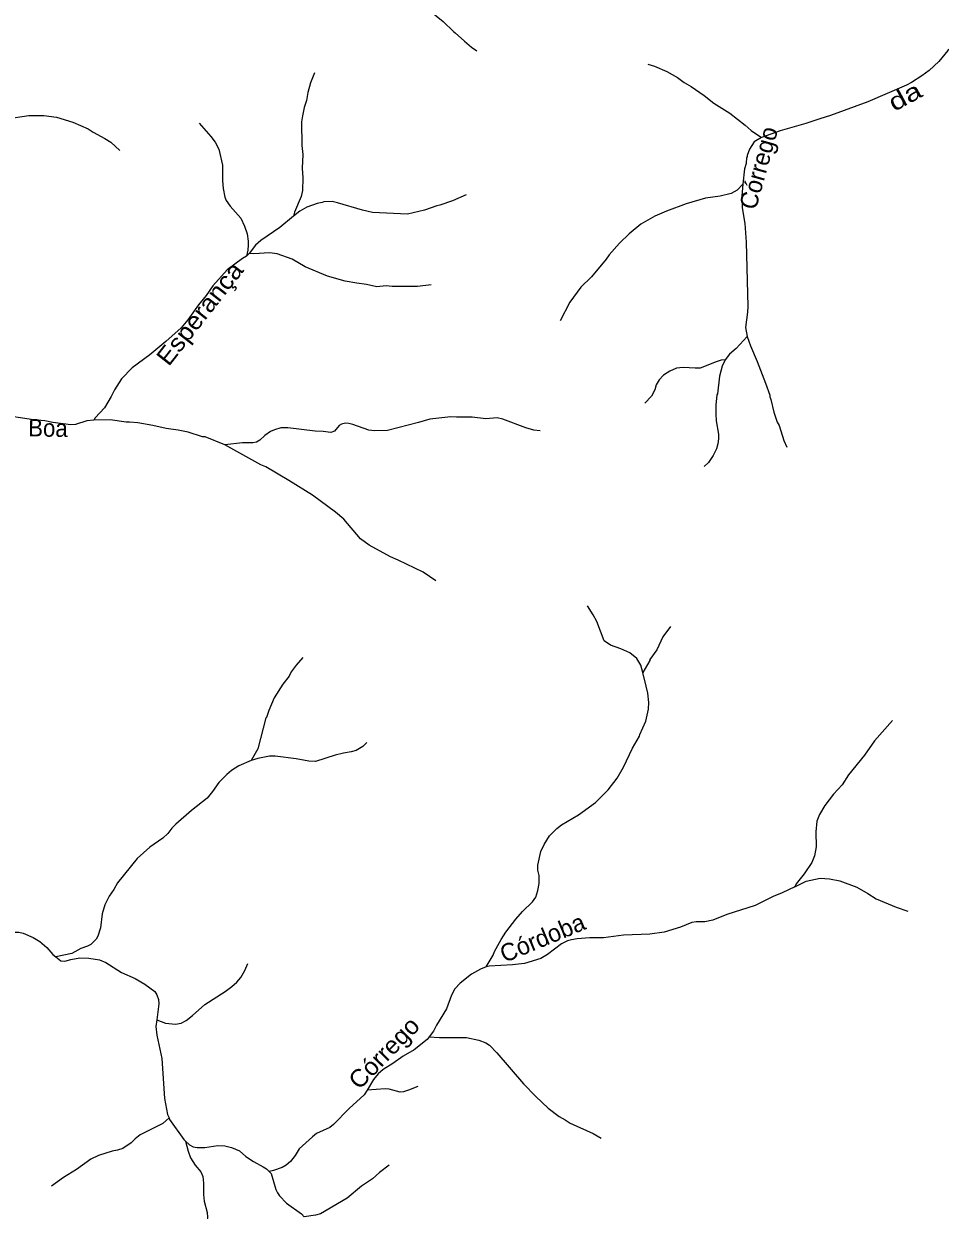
# Model space of a CAD drawing. Extents: x 551.6 to 577.6, y 7567 to 7594.7.
# Drawn here: x 563.33 to 568.58, y 7579.74 to 7586.53 of the extents above; entities that cross this region are included whole.
import ezdxf
from ezdxf.enums import TextEntityAlignment as Align

# ---------------------------------------------------------------- set-up
doc = ezdxf.new("R2010")
doc.units = 0
doc.header["$LTSCALE"] = 0.04
doc.layers.add('61', color=7, linetype='Continuous')
doc.layers.add('7', color=7, linetype='Continuous', lineweight=25)

msp = doc.modelspace()

# ---------------------------------------------------------------- linework, layer by layer
at = {"layer": '7'}
for points in [[(565.2572, 7587.1271), (565.3135, 7587.0152), (565.3787, 7586.9049), (565.4029, 7586.8695), (565.4978, 7586.7528), (565.5767, 7586.6796), (565.7377, 7586.5484), (565.7956, 7586.4897), (565.8061, 7586.4832), (565.8584, 7586.4349), (565.9002, 7586.4003), (565.93, 7586.3802)], [(568.8523, 7586.5323), (568.7734, 7586.4888), (568.6551, 7586.4035), (568.6285, 7586.381), (568.5762, 7586.3182), (568.5207, 7586.2675), (568.4788, 7586.2353), (568.4193, 7586.1975), (568.3919, 7586.183), (568.1698, 7586.0881), (567.9557, 7586.0084), (567.8945, 7585.9907)], [(566.9087, 7586.303), (566.9481, 7586.2909), (567.0181, 7586.2603), (567.0793, 7586.2265), (567.1171, 7586.1975), (567.1573, 7586.1742), (567.2314, 7586.1243), (567.2877, 7586.08), (567.3795, 7586.0221), (567.4664, 7585.9545), (567.501, 7585.9223), (567.5609, 7585.8836)], [(565.0005, 7586.2539), (564.9779, 7586.1967), (564.9618, 7586.1404), (564.9538, 7586.0953), (564.9409, 7586.0551), (564.9312, 7586.0068), (564.9264, 7585.973), (564.928, 7585.8362), (564.9329, 7585.7847), (564.9288, 7585.7074), (564.9337, 7585.6511), (564.9312, 7585.5786), (564.9232, 7585.5448), (564.8862, 7585.4547), (564.8806, 7585.4316)], [(562.9627, 7585.9166), (563.0191, 7585.9263), (563.2347, 7585.9907), (563.3635, 7586.0084), (563.4504, 7586.0092), (563.5229, 7586.0003), (563.6162, 7585.9714), (563.7039, 7585.9335), (563.7321, 7585.9134), (563.7997, 7585.878), (563.8335, 7585.8563), (563.8842, 7585.8088)], [(567.8945, 7585.9907), (567.8141, 7585.9633), (567.6676, 7585.9215), (567.5609, 7585.8836)], [(564.3389, 7585.9641), (564.4065, 7585.8893), (564.4307, 7585.8555), (564.4516, 7585.8169), (564.4725, 7585.7251), (564.4733, 7585.635), (564.4773, 7585.5899), (564.487, 7585.5416), (564.4942, 7585.5223), (564.516, 7585.4893), (564.5779, 7585.4209), (564.5997, 7585.3758), (564.6142, 7585.3308), (564.6206, 7585.2889), (564.6206, 7585.2535), (564.6174, 7585.2487), (564.6182, 7585.2374), (564.6102, 7585.2023)], [(567.5609, 7585.8836), (567.5195, 7585.8579), (567.4913, 7585.8169), (567.4776, 7585.7798), (567.4776, 7585.771), (567.4744, 7585.7686), (567.472, 7585.7348), (567.4631, 7585.7026), (567.4546, 7585.616)], [(567.4546, 7585.616), (567.4213, 7585.581), (567.3875, 7585.5625), (567.3231, 7585.5464), (567.2394, 7585.5352), (567.13, 7585.5038), (567.0165, 7585.4611), (566.9497, 7585.4321), (566.87, 7585.3863), (566.8016, 7585.3315), (566.7477, 7585.2784), (566.6881, 7585.2108), (566.6712, 7585.1859), (566.5867, 7585.0845), (566.5264, 7585.0249), (566.462, 7584.9396), (566.4065, 7584.8326)], [(567.4546, 7585.616), (567.4479, 7585.5481), (567.4503, 7585.4805), (567.4648, 7585.3903), (567.4736, 7585.2841)], [(565.8689, 7585.5537), (565.7908, 7585.5207), (565.7183, 7585.4949), (565.7006, 7585.4917), (565.6298, 7585.4667), (565.5333, 7585.4434), (565.3321, 7585.4531), (565.2741, 7585.4659), (565.1325, 7585.5094), (565.1003, 7585.5158), (565.0536, 7585.5142), (565.0439, 7585.511)], [(565.0439, 7585.511), (565.015, 7585.5046), (564.957, 7585.4837), (564.916, 7585.4603), (564.8806, 7585.4316)], [(564.8806, 7585.4316), (564.8009, 7585.367), (564.693, 7585.2929), (564.6616, 7585.2656), (564.6258, 7585.2185), (564.6102, 7585.2023)], [(567.4736, 7585.2841), (567.4817, 7584.9147), (567.4809, 7584.8817), (567.468, 7584.7948), (567.4789, 7584.7419)], [(564.6102, 7585.2023), (564.5868, 7585.1899), (564.4999, 7585.1239), (564.4178, 7585.033), (564.3791, 7584.9783), (564.3349, 7584.9235), (564.2753, 7584.8382), (564.2367, 7584.7923), (564.1482, 7584.7135), (564.0573, 7584.6386)], [(565.6677, 7585.0394), (565.5896, 7585.0289), (565.4447, 7585.0289), (565.4109, 7585.0322), (565.3562, 7585.0281), (565.2983, 7585.0402), (565.2419, 7585.0474), (565.1759, 7585.0603), (565.0745, 7585.0893), (564.9466, 7585.1424), (564.8717, 7585.1859), (564.7864, 7585.2165), (564.7413, 7585.2229), (564.6528, 7585.2173), (564.6258, 7585.2185)], [(567.4789, 7584.7419), (567.4157, 7584.6732), (567.377, 7584.641), (567.3532, 7584.6098)], [(567.4789, 7584.7419), (567.4969, 7584.6901), (567.5356, 7584.6), (567.5839, 7584.4745), (567.608, 7584.4068), (567.608, 7584.394), (567.6112, 7584.3924), (567.6144, 7584.3811), (567.6313, 7584.3087), (567.6507, 7584.2523), (567.6611, 7584.233), (567.6877, 7584.1461), (567.7054, 7584.1091)], [(564.0573, 7584.6386), (563.9558, 7584.5638), (563.8939, 7584.501), (563.8536, 7584.4374), (563.8351, 7584.3988), (563.7973, 7584.3344), (563.7426, 7584.2773), (563.7353, 7584.2636)], [(567.3532, 7584.6098), (567.3296, 7584.6064), (567.3006, 7584.5968), (567.2088, 7584.5614), (567.1799, 7584.5605), (567.1123, 7584.5654), (567.0736, 7584.5614), (567.035, 7584.5445), (566.9988, 7584.5219), (566.9746, 7584.4938), (566.9577, 7584.4664), (566.9489, 7584.4374), (566.9304, 7584.4004), (566.8926, 7584.361)], [(567.3532, 7584.6098), (567.3344, 7584.5726), (567.3199, 7584.5147), (567.3086, 7584.4141), (567.3054, 7584.4085), (567.2998, 7584.3489), (567.299, 7584.2974)], [(563.7353, 7584.2636), (563.6951, 7584.2604), (563.6307, 7584.2378), (563.605, 7584.2362), (563.5019, 7584.2507), (563.4553, 7584.2604), (563.3909, 7584.266), (563.1881, 7584.295), (563.0352, 7584.3336), (562.9563, 7584.3408), (562.9199, 7584.3408)], [(567.299, 7584.2974), (567.3006, 7584.2604), (567.3151, 7584.1831), (567.3151, 7584.1558), (567.311, 7584.1284), (567.303, 7584.0994), (567.2845, 7584.0608), (567.2571, 7584.0205), (567.2322, 7583.9988)], [(563.9398, 7584.2515), (563.9204, 7584.2515), (563.8287, 7584.2652), (563.7353, 7584.2636)], [(564.4866, 7584.1227), (564.3743, 7584.167), (564.3582, 7584.1686), (564.2762, 7584.1944), (564.2182, 7584.2064), (564.1506, 7584.2153), (564.0733, 7584.2338), (563.988, 7584.2475), (563.9398, 7584.2515)], [(565.3111, 7584.2056), (565.2194, 7584.2378), (565.1969, 7584.2443), (565.1775, 7584.2459), (565.155, 7584.2411), (565.1413, 7584.2322), (565.114, 7584.2008), (565.0938, 7584.1928), (565.0488, 7584.1992), (565.0037, 7584.2), (564.8476, 7584.2201), (564.8073, 7584.2201), (564.7703, 7584.2089), (564.7478, 7584.1976), (564.7148, 7584.175), (564.6874, 7584.1493), (564.6673, 7584.138), (564.6464, 7584.1332), (564.5884, 7584.1332), (564.4866, 7584.1227)], [(566.2922, 7584.2024), (566.256, 7584.2064), (566.2109, 7584.2193), (566.0789, 7584.27), (566.0467, 7584.2765), (565.9823, 7584.2716), (565.9035, 7584.2797), (565.8133, 7584.2797), (565.7811, 7584.2829), (565.6604, 7584.2684), (565.596, 7584.2491), (565.4174, 7584.204), (565.3449, 7584.2016), (565.3111, 7584.2056)], [(564.8524, 7583.9175), (564.7212, 7583.9956), (564.693, 7584.0077), (564.4866, 7584.1227)], [(565.695, 7583.3421), (565.6234, 7583.3928), (565.4801, 7583.462), (565.4351, 7583.4797), (565.3127, 7583.5465), (565.2628, 7583.5843), (565.1679, 7583.6954), (565.1212, 7583.7372), (564.9884, 7583.8338), (564.8524, 7583.9175)], [(566.8804, 7582.8186), (566.87, 7582.8592), (566.8467, 7582.8978), (566.8064, 7582.93), (566.7549, 7582.9534), (566.6954, 7582.9735), (566.6587, 7583), (566.6165, 7583.1095), (566.5972, 7583.1481), (566.5642, 7583.1988)], [(567.039, 7583.0813), (566.9947, 7583.0226), (566.9618, 7582.9469), (566.9207, 7582.893), (566.9207, 7582.8874), (566.8804, 7582.8186)], [(564.9329, 7582.9027), (564.8942, 7582.86), (564.8661, 7582.8214), (564.8548, 7582.7972), (564.8186, 7582.7506), (564.7687, 7582.6717), (564.7381, 7582.5993), (564.7252, 7582.559), (564.722, 7582.5574), (564.6753, 7582.3804), (564.6368, 7582.3131)], [(566.4153, 7581.9449), (566.5119, 7582.0021), (566.6093, 7582.0729), (566.6825, 7582.1462), (566.7332, 7582.213), (566.771, 7582.2757), (566.8209, 7582.3836), (566.8612, 7582.4528), (566.8628, 7582.4633), (566.8982, 7582.5397), (566.9127, 7582.6073), (566.9143, 7582.6459), (566.9102, 7582.6991), (566.9006, 7582.7393), (566.8804, 7582.8186)], [(568.3114, 7582.5421), (568.2076, 7582.427), (568.1504, 7582.345), (568.0587, 7582.2307), (568.0225, 7582.1743), (567.9726, 7582.1212), (567.9227, 7582.0552), (567.8929, 7582.0037), (567.8768, 7581.9651), (567.8712, 7581.9039), (567.8736, 7581.8186), (567.8639, 7581.7671), (567.8486, 7581.7285), (567.8044, 7581.6641), (567.7601, 7581.6069), (567.752, 7581.5901), (567.6789, 7581.5554)], [(565.2991, 7582.4174), (565.2765, 7582.3932), (565.2387, 7582.3715), (565.2097, 7582.3626), (565.1663, 7582.3562), (565.118, 7582.3433), (565.0053, 7582.3079), (564.9667, 7582.3103), (564.8959, 7582.324), (564.7751, 7582.3377), (564.7429, 7582.3377), (564.6753, 7582.3256), (564.6368, 7582.3131)], [(564.5248, 7582.2556), (564.4975, 7582.2331), (564.4516, 7582.1872), (564.4162, 7582.1357), (564.3848, 7582.0971), (564.2955, 7582.0278), (564.2061, 7581.9482), (564.182, 7581.9256), (564.1594, 7581.8959), (564.1313, 7581.8677), (564.0573, 7581.817), (563.9832, 7581.7518), (563.8721, 7581.6134)], [(564.6368, 7582.3131), (564.5659, 7582.2838), (564.5248, 7582.2556)], [(565.9842, 7581.1305), (566.0226, 7581.1973), (566.0306, 7581.219), (566.0684, 7581.2882), (566.0958, 7581.3293), (566.1538, 7581.4049), (566.1924, 7581.4484), (566.2495, 7581.5031), (566.2688, 7581.5305), (566.2801, 7581.5691), (566.2865, 7581.6094), (566.2865, 7581.6544), (566.2793, 7581.685), (566.2785, 7581.714), (566.297, 7581.7913), (566.3155, 7581.8315), (566.3469, 7581.8814), (566.388, 7581.924), (566.4153, 7581.9449)], [(567.752, 7581.5901), (567.8173, 7581.6222), (567.8961, 7581.6399), (567.9509, 7581.6351), (568.0088, 7581.6246), (568.107, 7581.5884), (568.1698, 7581.5522), (568.2181, 7581.52), (568.3324, 7581.4725), (568.3991, 7581.45)], [(563.8721, 7581.6134), (563.8496, 7581.574), (563.8238, 7581.5369), (563.7997, 7581.4862), (563.7844, 7581.4355), (563.7747, 7581.355), (563.7595, 7581.3068), (563.7498, 7581.2891), (563.7184, 7581.2585), (563.6999, 7581.2488), (563.6613, 7581.2367), (563.6098, 7581.2086), (563.5191, 7581.1888)], [(567.6789, 7581.5554), (567.6273, 7581.5337), (567.5243, 7581.483), (567.3618, 7581.4307), (567.2813, 7581.3985), (567.2362, 7581.3888), (567.1863, 7581.3888), (567.1606, 7581.3856), (567.0962, 7581.3582), (567.0028, 7581.3301), (566.9207, 7581.318), (566.771, 7581.3132), (566.6551, 7581.2971), (566.5779, 7581.2971), (566.5055, 7581.2923), (566.4717, 7581.2866)], [(563.24, 7581.325), (563.2565, 7581.3301), (563.3072, 7581.3301), (563.3313, 7581.3244), (563.3877, 7581.2995), (563.4263, 7581.2762), (563.4673, 7581.2416), (563.5019, 7581.2029), (563.5191, 7581.1888)], [(566.4717, 7581.2866), (566.4491, 7581.2794), (566.4153, 7581.2625), (566.334, 7581.2013), (566.2962, 7581.1796), (566.2029, 7581.1506), (566.1336, 7581.1426), (566, 7581.1361), (565.9842, 7581.1305)], [(563.5191, 7581.1888), (563.547, 7581.1659), (563.5695, 7581.1643), (563.605, 7581.1739), (563.6565, 7581.182), (563.708, 7581.1804), (563.7675, 7581.1707), (563.8053, 7581.1562), (563.8939, 7581.0983), (563.9727, 7581.0637), (564.0275, 7581.0315), (564.0846, 7580.9897), (564.0967, 7580.9704), (564.1055, 7580.9446), (564.1087, 7580.9188), (564.0973, 7580.828)], [(564.0973, 7580.828), (564.1458, 7580.8094), (564.2037, 7580.8029), (564.2359, 7580.8094), (564.2657, 7580.8247), (564.3011, 7580.852), (564.3711, 7580.9148), (564.4886, 7580.9904), (564.5273, 7581.0186), (564.5546, 7581.0444), (564.5771, 7581.071), (564.6005, 7581.1104), (564.619, 7581.1498)], [(565.9842, 7581.1305), (565.9501, 7581.1184), (565.8986, 7581.0886), (565.8342, 7581.0387), (565.8045, 7581.0058), (565.7851, 7580.9687), (565.7554, 7580.8915), (565.699, 7580.7965), (565.6821, 7580.7627), (565.6575, 7580.7305)], [(564.0973, 7580.828), (564.091, 7580.7901), (564.0967, 7580.7402)], [(564.0967, 7580.7402), (564.1256, 7580.6066), (564.1409, 7580.3764), (564.157, 7580.2847), (564.168, 7580.2661)], [(565.6575, 7580.7305), (565.6451, 7580.7144), (565.5711, 7580.6557), (565.5075, 7580.6202), (565.4496, 7580.5784)], [(565.6575, 7580.7305), (565.7168, 7580.7273), (565.8713, 7580.7265), (565.9421, 7580.712), (565.9807, 7580.6967), (566.0016, 7580.6822), (566.0451, 7580.6388), (566.198, 7580.4601), (566.2672, 7580.3877), (566.3381, 7580.3209), (566.4008, 7580.2742), (566.4354, 7580.2549), (566.4636, 7580.2347), (566.5972, 7580.1768), (566.6423, 7580.1503)], [(565.4496, 7580.5784), (565.3932, 7580.543), (565.3642, 7580.518), (565.3377, 7580.4859), (565.3022, 7580.4242)], [(565.3022, 7580.4242), (565.2845, 7580.3989), (565.1985, 7580.3201), (565.1083, 7580.2283), (565.0874, 7580.2114), (565.0117, 7580.176), (564.9876, 7580.1575), (564.9128, 7580.0891), (564.8894, 7580.0513), (564.862, 7580.0159), (564.8379, 7579.9949), (564.8154, 7579.9812), (564.7655, 7579.9643), (564.7399, 7579.9589)], [(565.592, 7580.4448), (565.5381, 7580.4239), (565.5091, 7580.4158), (565.4898, 7580.4142), (565.4286, 7580.4303), (565.4045, 7580.4327), (565.3022, 7580.4242)], [(564.168, 7580.2661), (564.1305, 7580.2331), (564.0017, 7580.168), (563.9735, 7580.1462), (563.9494, 7580.1221), (563.9011, 7580.0907), (563.8722, 7580.0802), (563.84, 7580.0754), (563.7627, 7580.0513), (563.7192, 7580.0287), (563.6363, 7579.97), (563.5615, 7579.9241), (563.4931, 7579.8742)], [(564.168, 7580.2661), (564.1691, 7580.2573), (564.2512, 7580.1414), (564.2614, 7580.1319)], [(564.2614, 7580.1319), (564.2761, 7580.0754), (564.2906, 7580.0368), (564.3156, 7579.9957), (564.3486, 7579.9563), (564.3598, 7579.9306), (564.3647, 7579.8919), (564.3647, 7579.8275), (564.3687, 7579.7889), (564.3856, 7579.7229), (564.3872, 7579.6972), (564.3824, 7579.6585), (564.3735, 7579.6199), (564.3462, 7579.5555), (564.3188, 7579.4396), (564.2971, 7579.3881), (564.2729, 7579.3455), (564.2504, 7579.3149), (564.1522, 7579.2094), (564.1144, 7579.1579), (564.0878, 7579.1064), (564.0009, 7578.9117)], [(564.2614, 7580.1319), (564.2842, 7580.1108), (564.3051, 7580.1003), (564.3277, 7580.0955), (564.3727, 7580.0955), (564.4468, 7580.1084), (564.4854, 7580.1052), (564.5248, 7580.0963), (564.5707, 7580.0762), (564.6069, 7580.0456), (564.6504, 7580.0166), (564.7059, 7579.9861)], [(564.7059, 7579.9861), (564.7252, 7579.974), (564.7399, 7579.9589)], [(564.7399, 7579.9589), (564.7518, 7579.9467), (564.7791, 7579.8565), (564.7872, 7579.8356), (564.7993, 7579.8195), (564.8403, 7579.7776), (564.9248, 7579.7156), (564.9404, 7579.6981)], [(565.4278, 7579.9949), (565.3715, 7579.9539), (565.332, 7579.916), (565.2693, 7579.8742), (565.1872, 7579.805), (565.0343, 7579.7165), (565.0053, 7579.7084), (564.9404, 7579.6981)]]:
    msp.add_lwpolyline(points, dxfattribs=at)

# ---------------------------------------------------------------- texts
at = {"layer": '61'}
for s, rotation, width, p in [('da', 28.346, 1.3, (568.4058, 7586.0752)), ('Esperança', 51.886, 1.1, (564.382, 7584.8438)), ('Boa', 358.975, 0.95, (563.4722, 7584.1689)), ('Córrego', 45.62, 1.05, (565.4336, 7580.6036))]:
    msp.add_text(s, height=0.1, rotation=rotation, dxfattribs=dict(at, width=width)).set_placement(p, align=Align.CENTER)
for s, rotation, p in [('Córrego', 74.554, (567.592, 7585.6956)), ('Córdoba', 22.548, (566.3251, 7581.2514))]:
    msp.add_text(s, height=0.1, rotation=rotation, dxfattribs=at).set_placement(p, align=Align.CENTER)

doc.saveas('drawing.dxf')
